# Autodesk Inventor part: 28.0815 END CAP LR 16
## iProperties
Created: 2009-01
Part Number: 28.0815 END CAP LR 16
Document SubType Name: Modeling
Designer: Administrator
Density: 1.06 g/cm^3
Material: ABS Plastic
Mass: 45.3114 g
Surface Area: 311.123 cm^2
Volume: 42.7466 cm^3
Author: Administrator
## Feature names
1. Base1
